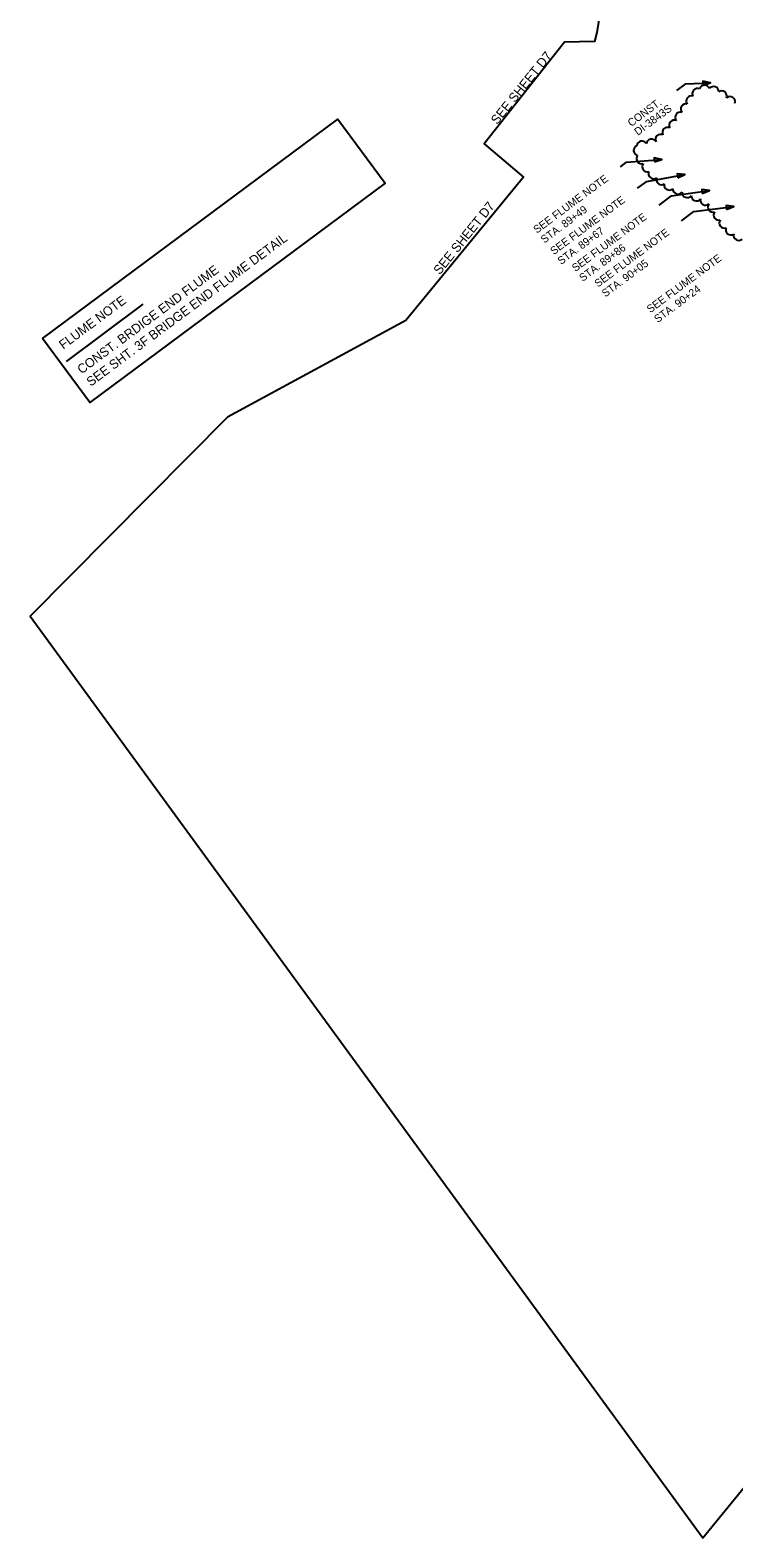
# Model space of a CAD drawing. Extents: x 1610466 to 1612467, y 1092226 to 1094137.
# Drawn here: x 1610466 to 1610924, y 1092449 to 1093429 of the extents above; entities that cross this region are included whole.
import ezdxf

# ---------------------------------------------------------------- set-up
doc = ezdxf.new("R2010")
doc.units = 0
for name, color, linetype in [('Default', 7, 'Continuous'), ('NOI', 7, 'Continuous'), ('Plan_Clip', 7, 'Continuous'), ('RD_SHT_MatchLine', 7, 'Continuous'), ('RD_TX_Drainage', 7, 'Continuous')]:
    doc.layers.add(name, color=color, linetype=linetype)

msp = doc.modelspace()

# ---------------------------------------------------------------- linework, layer by layer
at = {"layer": 'Default'}
for points in [[(1610850.27, 1093340.22), (1610854.21, 1093343.15), (1610877.07, 1093345.09)], [(1610861.21, 1093326.29), (1610867.24, 1093330.77), (1610892.12, 1093335.21)], [(1610875.26, 1093315.31), (1610883.4, 1093321.36), (1610908.01, 1093324.79)], [(1610889.97, 1093305.19), (1610897.96, 1093311.13), (1610923.89, 1093314.36)]]:
    msp.add_lwpolyline(points, dxfattribs=at)
for points in [[(1610872.37, 1093343.39), (1610877.07, 1093345.09), (1610872.15, 1093345.97)], [(1610887.6, 1093333.09), (1610892.12, 1093335.21), (1610887.14, 1093335.64)], [(1610903.4, 1093322.84), (1610908.01, 1093324.79), (1610903.05, 1093325.4)], [(1610919.26, 1093312.48), (1610923.89, 1093314.36), (1610918.94, 1093315.05)]]:
    msp.add_lwpolyline(points, close=True, dxfattribs=at)
at = {"layer": 'NOI'}
msp.add_lwpolyline([(1610474.32, 1093228.54), (1610666.34, 1093371.28), (1610697.27, 1093329.67), (1610505.25, 1093186.93)], close=True, dxfattribs=at)
at = {"layer": 'Plan_Clip'}
msp.add_lwpolyline([(1610846.86, 1093501.71), (1610834.81, 1093427.58), (1610833.33, 1093421.75), (1610813.84, 1093421.22), (1610761.65, 1093355.17), (1610787.25, 1093333.54), (1610710.55, 1093240.36), (1610594.61, 1093177.57), (1610466.33, 1093048.15), (1610903.72, 1092448.84), (1611131.37, 1092727.31), (1611304.36, 1092882.93), (1611360.44, 1092932.03), (1611366.57, 1092926.97), (1611396.45, 1092948.75), (1611405.31, 1092929.07), (1611472.85, 1092958.38), (1611477.73, 1092952.18), (1611593.22, 1093004.57), (1611593.81, 1093003.22), (1611687.06, 1093038.76), (1611716.3, 1093046.83), (1612140.14, 1093334.63)], dxfattribs=at)
at = {"layer": 'RD_TX_Drainage'}
msp.add_line((1610489.87, 1093213.75), (1610539.9, 1093250.94), dxfattribs=at)
msp.add_lwpolyline([(1610886.76, 1093389.76), (1610892.79, 1093394.25), (1610908.7, 1093394.85)], dxfattribs=at)
msp.add_lwpolyline([(1610903.92, 1093393.37), (1610908.7, 1093394.85), (1610903.83, 1093395.96)], close=True, dxfattribs=at)
for centre, start, end in [((1610900.26, 1093387.82), 65.10051, 210.10051), ((1610904.9, 1093389.97), 19.67365, 164.67365), ((1610910.73, 1093389.08), 357.99197, 142.99197), ((1610916.05, 1093386.26), 341.03832, 126.03832), ((1610892.7, 1093377.74), 74.1145, 219.1145), ((1610896.3, 1093382.96), 71.57952, 216.57952), ((1610921.36, 1093382.59), 344.72323, 129.72323), ((1610885.18, 1093367.25), 65.22646, 210.22646), ((1610889.18, 1093372.41), 74.1145, 219.1145), ((1610870.4, 1093354.83), 28.77075, 173.77075), ((1610876.3, 1093358.02), 63.06793, 208.06793), ((1610880.77, 1093362.58), 63.06793, 208.06793), ((1610862.09, 1093350.85), 112.55069, 257.55069), ((1610864.02, 1093345.53), 142.19825, 287.19825), ((1610864.14, 1093353.58), 28.77075, 173.77075), ((1610867.65, 1093340.28), 142.19825, 287.19825), ((1610871.77, 1093335.87), 158.9723, 303.9723), ((1610876.78, 1093331.91), 159.24735, 304.24735), ((1610881.94, 1093328.46), 168.29938, 313.29938), ((1610887.58, 1093325.85), 177.00777, 322.00777), ((1610893.57, 1093323.61), 177.00777, 322.00777), ((1610899.55, 1093321.38), 177.00777, 322.00777), ((1610905.46, 1093318.57), 167.09178, 312.09178), ((1610910.38, 1093314.06), 142.99711, 287.99711), ((1610914.09, 1093308.86), 142.99711, 287.99711), ((1610917.8, 1093303.66), 142.99711, 287.99711), ((1610921.96, 1093299.3), 159.3565, 304.3565), ((1610927.11, 1093295.74), 166.352, 311.352)]:
    msp.add_arc(centre, 3.35, start, end, dxfattribs=at)

# ---------------------------------------------------------------- texts
at = {"layer": 'Default'}
for s, p in [('SEE FLUME NOTE', (1610795.91, 1093296.69)), ('SEE FLUME NOTE', (1610806.85, 1093282.77)), ('STA. 89+49', (1610800.68, 1093290.27)), ('SEE FLUME NOTE', (1610820.89, 1093271.78)), ('STA. 89+67', (1610811.62, 1093276.35)), ('SEE FLUME NOTE', (1610835.61, 1093261.66)), ('STA. 89+86', (1610825.67, 1093265.36)), ('STA. 90+05', (1610840.38, 1093255.24)), ('SEE FLUME NOTE', (1610869.61, 1093244.97)), ('STA. 90+24', (1610874.38, 1093238.55))]:
    msp.add_text(s, height=5, rotation=36.62559, dxfattribs=at).set_placement(p)
at = {"layer": 'NOI'}
for s, p in [('SEE SHT. 3F BRIDGE END FLUME DETAIL', (1610505.78, 1093197.19)), ('CONST. BRDIGE END FLUME', (1610499.81, 1093205.22)), ('FLUME NOTE', (1610487.88, 1093221.27))]:
    msp.add_text(s, height=6, rotation=36.62709, dxfattribs=at).set_placement(p)
at = {"layer": 'RD_SHT_MatchLine'}
for p in [(1610770.04, 1093367.28), (1610732.68, 1093269.65)]:
    msp.add_text('SEE SHEET D7', height=6, rotation=51.16324, dxfattribs=at).set_placement(p)
at = {"layer": 'RD_TX_Drainage'}
for s, p in [('CONST.', (1610857.2, 1093366.05)), ('DI-3843S', (1610861.49, 1093360.27))]:
    msp.add_text(s, height=5, rotation=36.62559, dxfattribs=at).set_placement(p)

doc.saveas('drawing.dxf')
